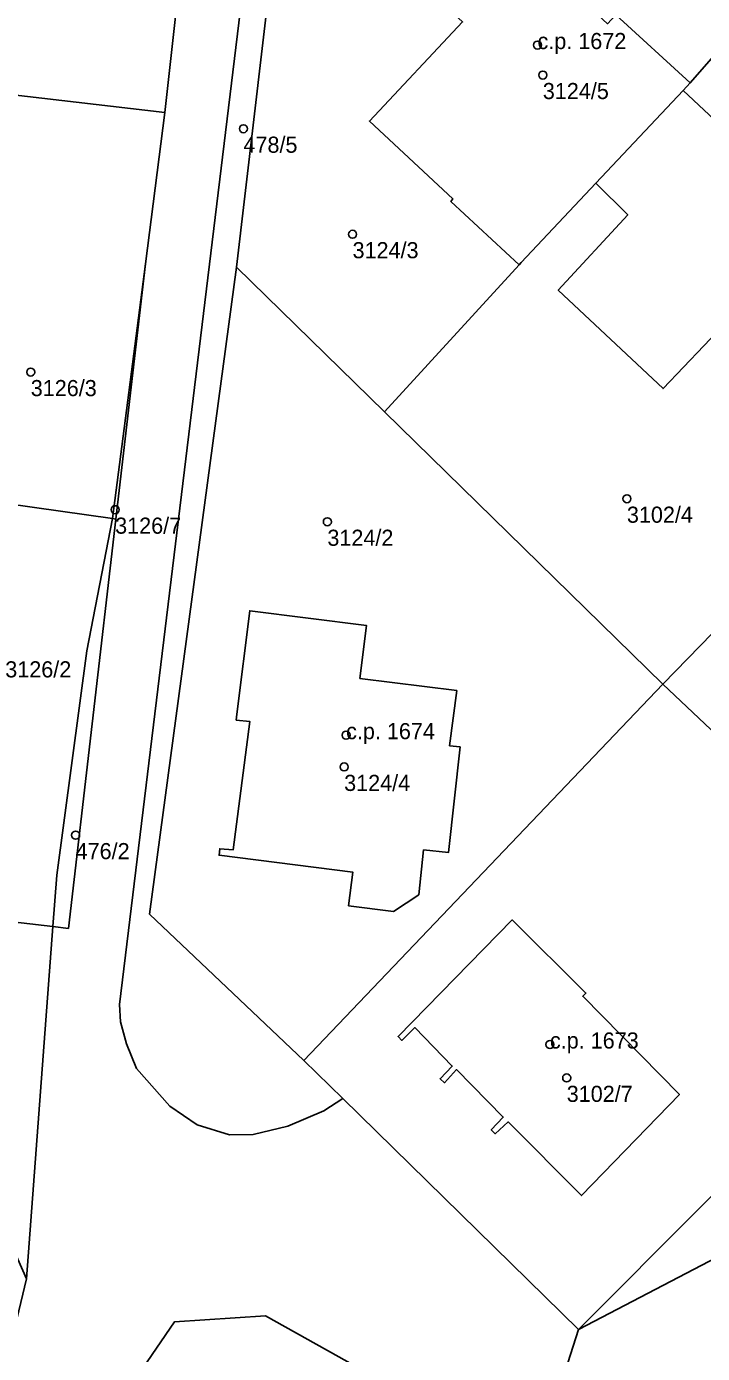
# Model space of a CAD drawing. Extents: x -878211 to -870363, y -1058464 to -1052522.
# Drawn here: x -874235.7 to -874193.8, y -1056727 to -1056644.7 of the extents above; entities that cross this region are included whole.
import ezdxf

# ---------------------------------------------------------------- set-up
doc = ezdxf.new("R2010")
doc.units = 0
for name, color, linetype in [('Vrstva 50', 7, 'Continuous'), ('Vrstva 51', 7, 'Continuous'), ('Vrstva 52', 7, 'Continuous')]:
    doc.layers.add(name, color=color, linetype=linetype)

msp = doc.modelspace()

# ---------------------------------------------------------------- linework, layer by layer
at = {"layer": 'Vrstva 50'}
for centre in [(-874204.07, -1056645.86994), (-874203.74, -1056647.72994), (-874222.29, -1056651.05994), (-874215.53, -1056657.59994), (-874235.47, -1056666.14994), (-874198.53, -1056673.99994), (-874230.24, -1056674.67994), (-874217.09, -1056675.42994), (-874215.93, -1056688.65994), (-874216.05, -1056690.62994), (-874232.69, -1056694.85994), (-874203.3, -1056707.83994), (-874202.26, -1056709.90994)]:
    msp.add_circle(centre, 0.25, dxfattribs=at)
at = {"layer": 'Vrstva 51'}
for points in [[(-874224.22, -1056623.66), (-874243.89, -1056621.38), (-874244.74, -1056637), (-874244.79, -1056637.85), (-874245.44, -1056647.92), (-874227.16, -1056650.06)], [(-874218.54, -1056708.84), (-874228.11, -1056699.76), (-874222.72, -1056659.65), (-874218.46, -1056623.34), (-874217.91, -1056622.88), (-874215.71, -1056622.66), (-874218.6, -1056622.25), (-874219.56, -1056623.35), (-874220.21, -1056624.92), (-874229.97, -1056705.36), (-874229.9, -1056706.43), (-874229.53, -1056707.8), (-874228.92, -1056709.33), (-874226.85, -1056711.66), (-874225.16, -1056712.82), (-874223.16, -1056713.44), (-874221.69, -1056713.43), (-874219.54, -1056712.91), (-874217.31, -1056711.95), (-874216.13, -1056711.19)], [(-874214.92, -1056638.31), (-874210.38, -1056633.52), (-874207.9, -1056635.89), (-874204.52, -1056632.21), (-874210.99, -1056628.12), (-874218.46, -1056623.34), (-874222.72, -1056659.65), (-874213.55, -1056668.61), (-874205.21, -1056659.49), (-874209.44, -1056655.56), (-874209.31, -1056655.41), (-874214.49, -1056650.58), (-874208.71, -1056644.43), (-874212.33, -1056641.11), (-874212.59, -1056641.37), (-874212.93, -1056641.1), (-874212.51, -1056640.58)], [(-874203.75, -1056640.8), (-874199.82, -1056636.59), (-874204.52, -1056632.21), (-874207.9, -1056635.89), (-874210.38, -1056633.52), (-874214.92, -1056638.31), (-874212.51, -1056640.58), (-874212.93, -1056641.1), (-874212.59, -1056641.37), (-874212.33, -1056641.11), (-874208.71, -1056644.43), (-874214.49, -1056650.58), (-874209.31, -1056655.41), (-874209.44, -1056655.56), (-874205.21, -1056659.49), (-874205.08, -1056659.35), (-874200.45, -1056654.43), (-874195.05, -1056648.69), (-874194.61, -1056648.22), (-874199.22, -1056644), (-874199.73, -1056644.55)], [(-874191.25, -1056644.37), (-874200.89, -1056634.68), (-874204.52, -1056632.21), (-874199.82, -1056636.59), (-874203.75, -1056640.8), (-874199.73, -1056644.55), (-874199.22, -1056644), (-874194.61, -1056648.22)], [(-874191.25, -1056644.37), (-874194.61, -1056648.22), (-874195.05, -1056648.69), (-874190.53, -1056652.92), (-874189.37, -1056651.72), (-874187.31, -1056653.66), (-874188.46, -1056654.88), (-874186.67, -1056656.47), (-874184.93, -1056654.62), (-874188.71, -1056651.06), (-874186.81, -1056649.1)], [(-874189.37, -1056651.72), (-874190.53, -1056652.92), (-874195.05, -1056648.69), (-874200.45, -1056654.43), (-874198.48, -1056656.4), (-874202.78, -1056661.06), (-874196.29, -1056667.17), (-874192.5, -1056663.2), (-874189.12, -1056666.32), (-874184.29, -1056661.14), (-874183.04, -1056659.78), (-874186.67, -1056656.47), (-874188.46, -1056654.88), (-874187.31, -1056653.66)], [(-874183.7, -1056661.69), (-874184.29, -1056661.14), (-874189.12, -1056666.32), (-874192.5, -1056663.2), (-874196.29, -1056667.17), (-874202.78, -1056661.06), (-874198.48, -1056656.4), (-874200.45, -1056654.43), (-874205.08, -1056659.35), (-874205.21, -1056659.49), (-874213.55, -1056668.61), (-874196.31, -1056685.5), (-874180.98, -1056669.75), (-874186.41, -1056664.47)], [(-874230.2, -1056675.26), (-874228.37, -1056659.44), (-874230.4, -1056675.23)], [(-874213.55, -1056668.61), (-874222.72, -1056659.65), (-874228.11, -1056699.76), (-874218.54, -1056708.84), (-874196.31, -1056685.5)], [(-874163.28, -1056673.71), (-874165.51, -1056675.95), (-874167.32, -1056677.74), (-874164.96, -1056680.14), (-874171.34, -1056686.4), (-874174.67, -1056683.01), (-874178.51, -1056686.83), (-874179.94, -1056685.41), (-874184.78, -1056680.61), (-874174.58, -1056670.46), (-874172.09, -1056672.95), (-874170.26, -1056671.16), (-874167.96, -1056668.92), (-874174.34, -1056662.37), (-874180.98, -1056669.75), (-874196.31, -1056685.5), (-874178.46, -1056702.37), (-874157.48, -1056679.66)], [(-874248.91, -1056683.91), (-874249.72, -1056689.8), (-874252.01, -1056689.47), (-874253.04, -1056698.33), (-874234.1, -1056700.53), (-874233.86, -1056697.34), (-874231.99, -1056683.43), (-874230.4, -1056675.23), (-874250.04, -1056672.45), (-874250.39, -1056675.44), (-874245.45, -1056676.12), (-874246.58, -1056684.24)], [(-874231.99, -1056683.43), (-874233.86, -1056697.34), (-874234.1, -1056700.53), (-874233.14, -1056700.64), (-874230.2, -1056675.26), (-874230.4, -1056675.23)], [(-874211.43, -1056698.55), (-874211.13, -1056695.77), (-874209.59, -1056695.94), (-874208.87, -1056689.39), (-874209.52, -1056689.32), (-874209.07, -1056685.9), (-874215.07, -1056685.14), (-874214.66, -1056681.87), (-874221.9, -1056680.95), (-874222.7, -1056687.35), (-874222.74, -1056687.72), (-874221.89, -1056687.82), (-874222.92, -1056695.76), (-874223.76, -1056695.7), (-874223.8, -1056696.11), (-874215.52, -1056697.15), (-874215.78, -1056699.24), (-874213, -1056699.59)], [(-874211.43, -1056698.55), (-874213, -1056699.59), (-874215.78, -1056699.24), (-874215.52, -1056697.15), (-874223.8, -1056696.11), (-874223.76, -1056695.7), (-874222.92, -1056695.76), (-874221.89, -1056687.82), (-874222.74, -1056687.72), (-874222.7, -1056687.35), (-874221.9, -1056680.95), (-874214.66, -1056681.87), (-874215.07, -1056685.14), (-874209.07, -1056685.9), (-874209.52, -1056689.32), (-874208.87, -1056689.39), (-874209.59, -1056695.94), (-874211.13, -1056695.77)], [(-874201.52, -1056725.52), (-874178.46, -1056702.37), (-874196.31, -1056685.5), (-874218.54, -1056708.84), (-874216.13, -1056711.19)], [(-874209.09, -1056709.4), (-874209.84, -1056710.21), (-874210.11, -1056709.96), (-874209.35, -1056709.18), (-874211.67, -1056706.79), (-874212.47, -1056707.59), (-874212.71, -1056707.35), (-874205.64, -1056700.11), (-874201.07, -1056704.65), (-874201.27, -1056704.85), (-874195.28, -1056710.94), (-874201.34, -1056717.21), (-874205.89, -1056712.64), (-874206.69, -1056713.37), (-874206.94, -1056713.13), (-874206.19, -1056712.34)], [(-874209.09, -1056709.4), (-874206.19, -1056712.34), (-874206.94, -1056713.13), (-874206.69, -1056713.37), (-874205.89, -1056712.64), (-874201.34, -1056717.21), (-874195.28, -1056710.94), (-874201.27, -1056704.85), (-874201.07, -1056704.65), (-874205.64, -1056700.11), (-874212.71, -1056707.35), (-874212.47, -1056707.59), (-874211.67, -1056706.79), (-874209.35, -1056709.18), (-874210.11, -1056709.96), (-874209.84, -1056710.21)], [(-874172.21, -1056708.46), (-874178.46, -1056702.37), (-874201.52, -1056725.52), (-874188.66, -1056718.8), (-874170.81, -1056709.82)], [(-874209.82, -1056740.99), (-874208.87, -1056739.35), (-874207.75, -1056740.01), (-874204.33, -1056733.94), (-874220.93, -1056724.66), (-874226.57, -1056725.04), (-874231.61, -1056732.41), (-874234.25, -1056743.88), (-874215.61, -1056748.94), (-874213.2, -1056749.67), (-874208.67, -1056741.64)]]:
    msp.add_lwpolyline(points, close=True, dxfattribs=at)
for points in [[(-874224.22, -1056623.66), (-874227.16, -1056650.06), (-874228.37, -1056659.44), (-874230.2, -1056675.26), (-874233.14, -1056700.64), (-874234.1, -1056700.53), (-874235.74, -1056722.36), (-874240.44, -1056741.96)], [(-874202.2, -1056727.57), (-874201.52, -1056725.52), (-874216.13, -1056711.19), (-874217.31, -1056711.95), (-874219.54, -1056712.91), (-874221.69, -1056713.43), (-874223.16, -1056713.44), (-874225.16, -1056712.82), (-874226.85, -1056711.66), (-874228.92, -1056709.33), (-874229.53, -1056707.8), (-874229.9, -1056706.43), (-874229.97, -1056705.36), (-874220.21, -1056624.92)], [(-874250.04, -1056672.45), (-874230.4, -1056675.23), (-874228.37, -1056659.44), (-874227.16, -1056650.06), (-874245.44, -1056647.92)], [(-874330.93, -1056687.7), (-874315.05, -1056691.82), (-874299.06, -1056695.85), (-874292.44, -1056697.51), (-874283, -1056699.87), (-874266.88, -1056704.53), (-874251.1, -1056710.27), (-874240.54, -1056715.05), (-874238.07, -1056717.12), (-874235.74, -1056722.36), (-874234.1, -1056700.53), (-874253.04, -1056698.33), (-874260.49, -1056697.46), (-874260.32, -1056695.27), (-874260.22, -1056694.01), (-874272.8, -1056691.04), (-874273.48, -1056690.86), (-874282.14, -1056688.64), (-874290.86, -1056686.36), (-874299.99, -1056684.08), (-874309.85, -1056681.63), (-874323.85, -1056678.09)], [(-874188.66, -1056718.8), (-874201.52, -1056725.52), (-874202.2, -1056727.57), (-874203.78, -1056732.28), (-874204.33, -1056733.94), (-874197.57, -1056737.94), (-874196.15, -1056738.78), (-874194.65, -1056739.67), (-874195.68, -1056741.36), (-874191.11, -1056744.25)], [(-874231.61, -1056732.41), (-874226.57, -1056725.04), (-874220.93, -1056724.66), (-874204.33, -1056733.94)]]:
    msp.add_lwpolyline(points, dxfattribs=at)
at = {"layer": 'Vrstva 52'}
for points in [[(-874214.92, -1056638.31), (-874212.51, -1056640.58), (-874212.93, -1056641.1), (-874212.59, -1056641.37), (-874212.33, -1056641.11), (-874208.71, -1056644.43), (-874214.49, -1056650.58), (-874209.31, -1056655.41), (-874209.44, -1056655.56), (-874205.21, -1056659.49), (-874205.08, -1056659.35), (-874200.45, -1056654.43), (-874195.05, -1056648.69), (-874194.61, -1056648.22), (-874199.22, -1056644), (-874199.73, -1056644.55), (-874203.75, -1056640.8), (-874199.82, -1056636.59), (-874204.52, -1056632.21), (-874207.9, -1056635.89), (-874210.38, -1056633.52)], [(-874198.48, -1056656.4), (-874202.78, -1056661.06), (-874196.29, -1056667.17), (-874192.5, -1056663.2), (-874189.12, -1056666.32), (-874184.29, -1056661.14), (-874183.04, -1056659.78), (-874186.67, -1056656.47), (-874188.46, -1056654.88), (-874187.31, -1056653.66), (-874189.37, -1056651.72), (-874190.53, -1056652.92), (-874195.05, -1056648.69), (-874200.45, -1056654.43)], [(-874223.76, -1056695.7), (-874223.8, -1056696.11), (-874215.52, -1056697.15), (-874215.78, -1056699.24), (-874213, -1056699.59), (-874211.43, -1056698.55), (-874211.13, -1056695.77), (-874209.59, -1056695.94), (-874208.87, -1056689.39), (-874209.52, -1056689.32), (-874209.07, -1056685.9), (-874215.07, -1056685.14), (-874214.66, -1056681.87), (-874221.9, -1056680.95), (-874222.7, -1056687.35), (-874222.74, -1056687.72), (-874221.89, -1056687.82), (-874222.92, -1056695.76)], [(-874212.71, -1056707.35), (-874212.47, -1056707.59), (-874211.67, -1056706.79), (-874209.35, -1056709.18), (-874210.11, -1056709.96), (-874209.84, -1056710.21), (-874209.09, -1056709.4), (-874206.19, -1056712.34), (-874206.94, -1056713.13), (-874206.69, -1056713.37), (-874205.89, -1056712.64), (-874201.34, -1056717.21), (-874195.28, -1056710.94), (-874201.27, -1056704.85), (-874201.07, -1056704.65), (-874205.64, -1056700.11)]]:
    msp.add_lwpolyline(points, close=True, dxfattribs=at)

# ---------------------------------------------------------------- texts
at = {"layer": 'Vrstva 50'}
for s, p in [('c.p. 1672', (-874204.07, -1056646.12)), ('3124/5', (-874203.74, -1056649.219)), ('478/5', (-874222.29, -1056652.549)), ('3124/3', (-874215.53, -1056659.089)), ('3126/3', (-874235.47, -1056667.639)), ('3102/4', (-874198.53, -1056675.489)), ('3126/7', (-874230.24, -1056676.169)), ('3124/2', (-874217.09, -1056676.919)), ('3126/2', (-874237.05, -1056685.079)), ('c.p. 1674', (-874215.93, -1056688.909)), ('3124/4', (-874216.05, -1056692.119)), ('476/2', (-874232.69, -1056696.349)), ('c.p. 1673', (-874203.3, -1056708.09)), ('3102/7', (-874202.26, -1056711.399))]:
    msp.add_text(s, height=0.999996, dxfattribs=at).set_placement(p)

doc.saveas('drawing.dxf')
